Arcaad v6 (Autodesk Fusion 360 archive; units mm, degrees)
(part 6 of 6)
sketch "Sketch15" plane through (-7.6, 0, 0) normal (-1, 0, 0) x axis (0, 0, 1)
  line L1 (-31.7108, -439.5896) -> (-36.3225, -439.5896)
  line L2 (-36.3225, -423.4241) -> (-31.942, -423.4241)
  line L3 (-36.3225, -410.4241) -> (-36.3225, -423.4241)
  line L4 (-227.6775, -420.4241) -> (-46.3225, -420.4241)
  line L5 (-237.6775, -423.4241) -> (-237.6775, -410.4241)
  line L6 (-137, -423.4241) -> (-237.6775, -423.4241)
  line L7 (-137, -439.5896) -> (-137, -423.4241)
  line L8 (-237.6775, -439.5896) -> (-137, -439.5896)
  line L9 (-237.6775, -442.5896) -> (-237.6775, -439.5896)
  line L10 (-36.3225, -442.5896) -> (-237.6775, -442.5896)
  line L11 (-36.3225, -439.5896) -> (-36.3225, -442.5896)
  line L12 (-237.6775, -439.5896) -> (-237.6775, -423.4241)
  line L13 (-36.3225, -439.5896) -> (-36.3225, -423.4241)
  line L14 (-46.3225, -420.4241) -> (-227.6775, -420.4241)
  line L15
  line L16 (-227.6775, -442.5896) -> (-46.3225, -442.5896)
  line L17 (-227.6775, -420.4241) -> (-227.6775, -442.5896)
  line L18 (-242.058, -423.4241) -> (-137, -423.4241)
  line L19 (-137, -439.5896) -> (-242.2892, -439.5896)
  line L20 (-137, -423.4241) -> (-137, -439.5896)
  line L21 (-246.9266, -427.7712) -> (-237.6775, -427.7712)
  line L22 (-247.5, -435.3712) -> (-237.6775, -435.3712)
  line L23 (-42, -408.4241) -> (-38.3225, -408.4241)
  line L24 (-44, -417) -> (-44, -410.4241)
  line L25 (-230, -410.4241) -> (-230, -417)
  line L26 (-235.6775, -408.4241) -> (-232, -408.4241)
  circle C1 centre (-36.3225, -431.5712) radius 3.8
  arc A1 centre (-36.3225, -431.5712) radius 9.25 clockwise from (-31.942, -423.4241) to (-31.7108, -439.5896)
  circle C2 centre (-237.6775, -431.5712) radius 3.8
  arc A2 centre (-237.6775, -431.5712) radius 9.25 clockwise from (-242.2892, -439.5896) to (-242.058, -423.4241)
  arc A3 centre (-38.3225, -410.4241) radius 2 clockwise from (-38.3225, -408.4241) to (-36.3225, -410.4241)
  arc A4 centre (-42, -410.4241) radius 2 clockwise from (-44, -410.4241) to (-42, -408.4241)
  arc A5 centre (-47.6854, -417) radius 3.6854 clockwise from (-44, -417) to (-46.3225, -420.4241)
  arc A6 centre (-226.3146, -417) radius 3.6854 clockwise from (-227.6775, -420.4241) to (-230, -417)
  arc A7 centre (-232, -410.4241) radius 2 clockwise from (-232, -408.4241) to (-230, -410.4241)
  arc A8 centre (-235.6775, -410.4241) radius 2 clockwise from (-237.6775, -410.4241) to (-235.6775, -408.4241)
  point P9 (-237.6775, -423.4241)
  point P15 (-237.6775, -423.4241)
  point P12 (-237.6775, -439.5896)
  point P16 (-237.6775, -439.5896)
  point P6 (-36.3225, -423.4241)
  point P17 (-36.3225, -423.4241)
  point P3 (-36.3225, -439.5896)
  point P18 (-36.3225, -439.5896)
  point P28 (-237.6775, -427.7712)
  point P30 (-237.6775, -435.3712)
  coincident P9 P15
  coincident P12 P16
  coincident P6 P17
  coincident P3 P18
  coincident C2 P28
  coincident L12 P28
  tangent C2 L21
  coincident L12 P30
  coincident C2 P30
  tangent C2 L22
extrude "Extrude15" new body sketch "Sketch15" profile of C1 L1 A1 L2 L3 L4 L5 L6 L7 L8 L9 L10 L11 L12 L13 L14 L15 L16 L17 C2 L18 A2 L19 L20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 along normal blind 3
sketch "Sketch16" plane through (-11.1, 0, 0) normal (-1, 0, 0) x axis (0, 0, 1)
  circle C1 centre (-237.6775, -431.5712) radius 1.65
  circle C2 centre (-237.6775, -431.5712) radius 3.5
  circle C3 centre (-237.6775, -431.5712) radius 9.25
  circle C4 centre (-36.3225, -431.5712) radius 9.25
  circle C5 centre (-36.3225, -431.5712) radius 1.65
  circle C6 centre (-36.3225, -431.5712) radius 1.65
  circle C7 centre (-237.6775, -431.5712) radius 1.65
  circle C8 centre (-237.6775, -431.5712) radius 1.65
  point P4 (-246.111, -435.3712)
  point P5 (-36.3225, -431.5712)
  point P6 (-36.3225, -431.5712)
  concentric C1 C3
  coincident C3 P4
  coincident P5 P6
extrude "Extrude16" new body sketch "Sketch16" along normal blind 3
sketch "Sketch17" plane through (-10.6, 0, 0) normal (-1, 0, 0) x axis (0, 0, 1)
  line L1 (-246.111, -435.3712) -> (-237.6775, -435.3712)
  line L2 (-36.3225, -442.5896) -> (-237.6775, -442.5896)
  line L3 (-36.3225, -439.5896) -> (-36.3225, -442.5896)
  line L4 (-31.7108, -439.5896) -> (-36.3225, -439.5896)
  line L5 (-36.3225, -423.4241) -> (-31.942, -423.4241)
  line L6 (-36.3225, -410.4241) -> (-36.3225, -423.4241)
  line L7 (-227.6775, -420.4241) -> (-46.3225, -420.4241)
  line L8 (-237.6775, -427.7712) -> (-246.111, -427.7712)
  line L9 (-237.6775, -439.5896) -> (-242.2892, -439.5896)
  line L10 (-237.6775, -442.5896) -> (-237.6775, -439.5896)
  line L11 (-237.6775, -423.4241) -> (-237.6775, -410.4241)
  line L12 (-242.058, -423.4241) -> (-237.6775, -423.4241)
  line L13 (-42, -408.4241) -> (-38.3225, -408.4241)
  line L14 (-44, -417) -> (-44, -410.4241)
  line L15 (-230, -410.4241) -> (-230, -417)
  line L16 (-235.6775, -408.4241) -> (-232, -408.4241)
  circle C1 centre (-36.3225, -431.5712) radius 3.8
  arc A1 centre (-237.6775, -431.5712) radius 3.8 clockwise from (-237.6775, -427.7712) to (-237.6775, -435.3712)
  arc A2 centre (-237.6775, -431.5712) radius 9.25 clockwise from (-242.2892, -439.5896) to (-246.111, -435.3712)
  arc A3 centre (-36.3225, -431.5712) radius 9.25 clockwise from (-31.942, -423.4241) to (-31.7108, -439.5896)
  arc A4 centre (-237.6775, -431.5712) radius 9.25 clockwise from (-246.111, -427.7712) to (-242.058, -423.4241)
  circle C2 centre (-237.6775, -431.5712) radius 1.65
  circle C3 centre (-237.6775, -431.5712) radius 9.25
  circle C4 centre (-36.3225, -431.5712) radius 1.65
  circle C5 centre (-36.3225, -431.5712) radius 9.25
  circle C6 centre (-36.3225, -431.5712) radius 10
  circle C7 centre (-237.6775, -431.5712) radius 10
  arc A5 centre (-38.3225, -410.4241) radius 2 clockwise from (-38.3225, -408.4241) to (-36.3225, -410.4241)
  arc A6 centre (-42, -410.4241) radius 2 clockwise from (-44, -410.4241) to (-42, -408.4241)
  arc A7 centre (-47.6854, -417) radius 3.6854 clockwise from (-44, -417) to (-46.3225, -420.4241)
  arc A8 centre (-226.3146, -417) radius 3.6854 clockwise from (-227.6775, -420.4241) to (-230, -417)
  arc A9 centre (-232, -410.4241) radius 2 clockwise from (-232, -408.4241) to (-230, -410.4241)
  arc A10 centre (-235.6775, -410.4241) radius 2 clockwise from (-237.6775, -410.4241) to (-235.6775, -408.4241)
  concentric C1 C6
  concentric A1 C7
  dimension "d239" diameter C7 = 20
  dimension "d240" diameter C6 = 20
extrude "Extrude17" new body sketch "Sketch17" profile of L2 L3 L6 L7 C6 C7 along normal blind 6
sketch "Sketch18" plane through (-4.6, 0, 0) normal (-1, 0, 0) x axis (0, 0, 1)
  line L1 (-36.3225, -410.4241) -> (-36.3225, -421.5712)
  line L2 (-227.6775, -420.4241) -> (-46.3225, -420.4241)
  line L3 (-237.6775, -421.5712) -> (-237.6775, -410.4241)
  line L4 (-237.6775, -442.5896) -> (-237.6775, -441.5712)
  line L5 (-36.3225, -442.5896) -> (-237.6775, -442.5896)
  line L6 (-36.3225, -441.5712) -> (-36.3225, -442.5896)
  line L7 (-42, -408.4241) -> (-38.3225, -408.4241)
  line L8 (-44, -417) -> (-44, -410.4241)
  line L9 (-230, -410.4241) -> (-230, -417)
  line L10 (-235.6775, -408.4241) -> (-232, -408.4241)
  arc A1 centre (-237.6775, -431.5712) radius 10 clockwise from (-237.6775, -421.5712) to (-237.6775, -441.5712)
  arc A2 centre (-36.3225, -431.5712) radius 10 clockwise from (-36.3225, -441.5712) to (-36.3225, -421.5712)
  circle C1 centre (-237.6775, -431.5712) radius 1.65
  circle C2 centre (-237.6775, -431.5712) radius 9.25
  circle C3 centre (-36.3225, -431.5712) radius 1.65
  circle C4 centre (-36.3225, -431.5712) radius 9.25
  circle C5 centre (-36.3225, -431.5712) radius 10
  circle C6 centre (-237.6775, -431.5712) radius 10
  arc A3 centre (-38.3225, -410.4241) radius 2 clockwise from (-38.3225, -408.4241) to (-36.3225, -410.4241)
  arc A4 centre (-42, -410.4241) radius 2 clockwise from (-44, -410.4241) to (-42, -408.4241)
  arc A5 centre (-47.6854, -417) radius 3.6854 clockwise from (-44, -417) to (-46.3225, -420.4241)
  arc A6 centre (-226.3146, -417) radius 3.6854 clockwise from (-227.6775, -420.4241) to (-230, -417)
  arc A7 centre (-232, -410.4241) radius 2 clockwise from (-232, -408.4241) to (-230, -410.4241)
  arc A8 centre (-235.6775, -410.4241) radius 2 clockwise from (-237.6775, -410.4241) to (-235.6775, -408.4241)
  point P2 (-36.3225, -421.5712)
  point P5 (-237.6775, -421.5712)
  concentric C3 C5
  coincident P2 C5
  concentric A1 C6
  coincident P5 C6
sketch "Sketch19" plane through (-16.6, 0, 0) normal (-1, 0, 0) x axis (0, 0, 1)
  line L1 (-36.3225, -410.4241) -> (-36.3225, -421.5712)
  line L2 (-227.6775, -420.4241) -> (-46.3225, -420.4241)
  line L3 (-237.6775, -421.5712) -> (-237.6775, -410.4241)
  line L4 (-237.6775, -442.5896) -> (-237.6775, -441.5712)
  line L5 (-36.3225, -442.5896) -> (-237.6775, -442.5896)
  line L6 (-36.3225, -441.5712) -> (-36.3225, -442.5896)
  line L7 (-42, -408.4241) -> (-38.3225, -408.4241)
  line L8 (-44, -417) -> (-44, -410.4241)
  line L9 (-230, -410.4241) -> (-230, -417)
  line L10 (-235.6775, -408.4241) -> (-232, -408.4241)
  arc A1 centre (-237.6775, -431.5712) radius 10 clockwise from (-237.6775, -421.5712) to (-237.6775, -441.5712)
  arc A2 centre (-36.3225, -431.5712) radius 10 clockwise from (-36.3225, -441.5712) to (-36.3225, -421.5712)
  circle C1 centre (-237.6775, -431.5712) radius 1.65
  circle C2 centre (-237.6775, -431.5712) radius 9.25
  circle C3 centre (-36.3225, -431.5712) radius 1.65
  circle C4 centre (-36.3225, -431.5712) radius 9.25
  circle C5 centre (-36.3225, -431.5712) radius 10
  circle C6 centre (-237.6775, -431.5712) radius 10
  arc A3 centre (-38.3225, -410.4241) radius 2 clockwise from (-38.3225, -408.4241) to (-36.3225, -410.4241)
  arc A4 centre (-42, -410.4241) radius 2 clockwise from (-44, -410.4241) to (-42, -408.4241)
  arc A5 centre (-47.6854, -417) radius 3.6854 clockwise from (-44, -417) to (-46.3225, -420.4241)
  arc A6 centre (-226.3146, -417) radius 3.6854 clockwise from (-227.6775, -420.4241) to (-230, -417)
  arc A7 centre (-232, -410.4241) radius 2 clockwise from (-232, -408.4241) to (-230, -410.4241)
  arc A8 centre (-235.6775, -410.4241) radius 2 clockwise from (-237.6775, -410.4241) to (-235.6775, -408.4241)
  point P2 (-36.3225, -421.5712)
  point P5 (-237.6775, -421.5712)
  concentric A2 C5
  coincident P2 C5
  concentric A1 C6
  coincident P5 C6
extrude "Extrude18" new body sketch "Sketch19" profile of L1 L2 L3 A1 L4 L5 L6 A2 C1 C2 C3 C4 C5 C6 along normal blind 3
offset_faces "OffsetFaces1" distance 8
sketch "Sketch20" plane through (0, -420.4241, 0) normal (0, 1, 0) x axis (-1, 0, 0)
  line L1 (4.6, -34.3231) -> (0, -34.3231)
  line L2 (4.6, -24.8497) -> (4.6, -34.3231)
  line L3 (10.6, -24.8497) -> (4.6, -24.8497)
  line L4 (13, -24.8497) -> (10.6, -24.8497)
  line L5 (13, -21.8852) -> (13, -24.8497)
  line L6
  line L7 (3.6, -20.1102) -> (3.6, -21.8852)
  line L8 (13, -20.1102) -> (3.6, -20.1102)
  line L9 (13, -17.6854) -> (13, -20.1102)
  line L10 (0, -17.6854) -> (13, -17.6854)
  line L11 (0, -18.7497) -> (0, -17.6854)
  line L12 (-5.9, -18.7497) -> (0, -18.7497)
  line L13 (-5.9, -17.8497) -> (-5.9, -18.7497)
  line L14 (-7.1493, -18.2329) -> (-5.9, -17.8497)
  line L15 (-7.856, -20.4822) -> (-7.856, -19.1889)
  line L16 (0.6, -20.4822) -> (-7.856, -20.4822)
  line L17 (-5.9, -21.6169) -> (0.6, -21.601)
  line L18
  line L19 (5.2687, -23.0039) -> (-5.9, -23.0039)
  line L20 (-7.856, -24.0039) -> (5.2687, -24.0039)
  line L21 (-7.856, -24.4104) -> (-7.856, -24.0039)
  line L22 (-5.9, -25.7497) -> (-7.1493, -25.3665)
  line L23 (-5.9, -24.8497) -> (-5.9, -25.7497)
  line L24 (0, -24.8497) -> (-5.9, -24.8497)
  line L25 (0, -34.3231) -> (0, -24.8497)
  arc A1 centre (-6.856, -19.1889) radius 1 clockwise from (-7.856, -19.1889) to (-7.1493, -18.2329)
  arc A2 centre (0.6, -21.0416) radius 0.5594 clockwise from (0.6, -20.4822) to (0.6, -21.601)
  arc A3 centre (5.2687, -23.5039) radius 0.5 clockwise from (5.2687, -23.0039) to (5.2687, -24.0039)
  arc A4 centre (-6.856, -24.4104) radius 1 clockwise from (-7.1493, -25.3665) to (-7.856, -24.4104)
sketch "Sketch21" plane through (0, -442.5896, 0) normal (0, -1, 0) x axis (1, 0, 0)
  line L1 (5.9, -17.8497) -> (7.1493, -18.2329)
  line L2 (5.9, -18.7497) -> (5.9, -17.8497)
  line L3 (0, -18.7497) -> (5.9, -18.7497)
  line L4 (0, -17.6854) -> (0, -18.7497)
  line L5 (-13, -17.6854) -> (0, -17.6854)
  line L6 (-13, -20.1102) -> (-13, -17.6854)
  line L7 (-3.6, -20.1102) -> (-13, -20.1102)
  line L8 (-3.6, -21.8852) -> (-3.6, -20.1102)
  line L9
  line L10 (-13, -24.8497) -> (-13, -21.8852)
  line L11 (-10.6, -24.8497) -> (-13, -24.8497)
  line L12 (-4.6, -24.8497) -> (-10.6, -24.8497)
  line L13 (-4.6, -34.3231) -> (-4.6, -24.8497)
  line L14 (0, -34.3231) -> (-4.6, -34.3231)
  line L15 (0, -24.8497) -> (0, -34.3231)
  line L16 (5.9, -24.8497) -> (0, -24.8497)
  line L17 (5.9, -25.7497) -> (5.9, -24.8497)
  line L18 (7.1493, -25.3665) -> (5.9, -25.7497)
  line L19 (7.856, -24.0039) -> (7.856, -24.4104)
  line L20 (-5.2687, -24.0039) -> (7.856, -24.0039)
  line L21 (5.9, -23.0039) -> (-5.2687, -23.0039)
  line L22 (5.9, -21.6169) -> (5.9, -23.0039)
  line L23
  line L24 (7.856, -20.4822) -> (-0.6, -20.4822)
  line L25 (7.856, -19.1889) -> (7.856, -20.4822)
  line L26 (7.856, -20.4822) -> (7.856, -24.0039)
  arc A1 centre (6.856, -19.1889) radius 1 clockwise from (7.1493, -18.2329) to (7.856, -19.1889)
  arc A2 centre (6.856, -24.4104) radius 1 clockwise from (7.856, -24.4104) to (7.1493, -25.3665)
  arc A3 centre (-5.2687, -23.5039) radius 0.5 clockwise from (-5.2687, -24.0039) to (-5.2687, -23.0039)
  arc A4 centre (-0.6, -21.0416) radius 0.5594 clockwise from (-0.6, -21.601) to (-0.6, -20.4822)
  point P25 (7.856, -24.0039)
  point P35 (7.856, -24.0039)
  point P34 (7.856, -20.4822)
  point P36 (7.856, -20.4822)
  coincident P25 P35
  coincident P34 P36
extrude "Extrude25" add sketch "Sketch21" profile of L20 A3 L21 L22 L23 A4 L24 L26 to an object
sketch "Sketch22" plane through (7.856, 0, 0) normal (1, 0, 0) x axis (0, 0, -1)
  line L1 (24.4104, -420.4241) -> (24.4104, -442.5896)
  line L2 (19.1889, -420.4241) -> (24.4104, -420.4241)
  line L3
  line L4 (24.4104, -442.5896) -> (19.1889, -442.5896)
  line L5
  line L6 (19.1889, -442.5896) -> (24.4104, -420.4241)
  circle C1 centre (21.7997, -431.5069) radius 2.6108
  point P4 (19.1889, -420.4241)
  point P6 (19.1889, -420.4241)
  point P2 (24.4104, -442.5896)
  point P7 (24.4104, -442.5896)
  point P3 (24.4104, -420.4241)
  point P8 (24.4104, -420.4241)
  point P5 (19.1889, -442.5896)
  point P9 (19.1889, -442.5896)
  point P10 (21.7997, -431.5069)
  coincident P4 P6
  coincident P2 P7
  coincident P3 P8
  coincident P5 P9
  midpoint L5 P10
  tangent L1 C1
sketch "Sketch23" plane through (0, -420.4241, 0) normal (0, 1, 0) x axis (-1, 0, 0)
  line L1 (4.6, -34.3231) -> (0, -34.3231)
  line L2 (4.6, -24.8497) -> (4.6, -34.3231)
  line L3 (10.6, -24.8497) -> (4.6, -24.8497)
  line L4 (13, -24.8497) -> (10.6, -24.8497)
  line L5 (13, -21.8852) -> (13, -24.8497)
  line L6
  line L7 (3.6, -20.1102) -> (3.6, -21.8852)
  line L8 (13, -20.1102) -> (3.6, -20.1102)
  line L9 (13, -17.6854) -> (13, -20.1102)
  line L10 (0, -17.6854) -> (13, -17.6854)
  line L11 (0, -18.7497) -> (0, -17.6854)
  line L12 (-5.9, -18.7497) -> (0, -18.7497)
  line L13 (-5.9, -17.8497) -> (-5.9, -18.7497)
  line L14 (-7.1493, -18.2329) -> (-5.9, -17.8497)
  line L15 (-7.856, -24.4104) -> (-7.856, -19.1889)
  line L16 (-5.9, -25.7497) -> (-7.1493, -25.3665)
  line L17 (-5.9, -24.8497) -> (-5.9, -25.7497)
  line L18 (0, -24.8497) -> (-5.9, -24.8497)
  line L19 (0, -34.3231) -> (0, -24.8497)
  line L20 (0, -24.8497) -> (0, -18.7497)
  line L21 (-5.9, -25.7497) -> (-5.9, -24.8497)
  line L22 (-7.6602, -25.0049) -> (-7.3865, -25.2582)
  line L23 (-7.856, -19.1889) -> (-7.7837, -24.7838)
  line L24 (-5.9, -17.8497) -> (-7.4396, -18.3769)
  line L25 (0, -18.7497) -> (-5.9, -18.7497)
  arc A1 centre (-6.856, -19.1889) radius 1 clockwise from (-7.856, -19.1889) to (-7.1493, -18.2329)
  arc A2 centre (-6.856, -24.4104) radius 1 clockwise from (-7.1493, -25.3665) to (-7.856, -24.4104)
  point P13 (0, -18.7497)
  point P25 (0, -18.7497)
  point P24 (0, -24.8497)
  point P26 (0, -24.8497)
  point P23 (-5.9, -24.8497)
  point P27 (-5.9, -24.8497)
  point P22 (-5.9, -25.7497)
  point P28 (-5.9, -25.7497)
  point P29 (-7.3865, -25.2582)
  point P30 (-7.6602, -25.0049)
  point P31 (-7.7837, -24.7838)
  point P17 (-7.856, -19.1889)
  point P32 (-7.856, -19.1889)
  point P33 (-7.4396, -18.3769)
  point P15 (-5.9, -17.8497)
  point P34 (-5.9, -17.8497)
  point P14 (-5.9, -18.7497)
  point P35 (-5.9, -18.7497)
  point P36 (0, -18.7497)
  coincident P13 P25
  coincident P24 P26
  coincident P23 P27
  coincident P22 P28
  coincident A2 P29
  midpoint A2 P30
  coincident A2 P31
  coincident P17 P32
  coincident A1 P33
  coincident P15 P34
  coincident P14 P35
  coincident P13 P36
sketch "Sketch24" plane through (0, -420.4241, 0) normal (0, 1, 0) x axis (-1, 0, 0)
  line L1 (4.6, -34.3231) -> (0, -34.3231)
  line L2 (4.6, -24.8497) -> (4.6, -34.3231)
  line L3 (10.6, -24.8497) -> (4.6, -24.8497)
  line L4 (13, -24.8497) -> (10.6, -24.8497)
  line L5 (13, -21.8852) -> (13, -24.8497)
  line L6
  line L7 (3.6, -20.1102) -> (3.6, -21.8852)
  line L8 (13, -20.1102) -> (3.6, -20.1102)
  line L9 (13, -17.6854) -> (13, -20.1102)
  line L10 (0, -17.6854) -> (13, -17.6854)
  line L11 (0, -18.7497) -> (0, -17.6854)
  line L12 (-5.9, -18.7497) -> (0, -18.7497)
  line L13 (-5.9, -17.8497) -> (-5.9, -18.7497)
  line L14 (-7.1493, -18.2329) -> (-5.9, -17.8497)
  line L15 (-7.856, -24.4104) -> (-7.856, -19.1889)
  line L16 (-5.9, -25.7497) -> (-7.1493, -25.3665)
  line L17 (-5.9, -24.8497) -> (-5.9, -25.7497)
  line L18 (0, -24.8497) -> (-5.9, -24.8497)
  line L19 (0, -34.3231) -> (0, -24.8497)
  line L20 (-2.6535, -20.1403) -> (-7.856, -19.1889)
  line L21 (-2.6535, -20.727) -> (-2.6535, -20.1403)
  line L22 (-7.856, -20.4822) -> (-7.856, -19.1889)
  line L23 (-7.856, -19.8356) -> (-2.6535, -20.727)
  line L24
  line L25 (-2.6535, -23.459) -> (-7.856, -24.4104)
  line L26 (-7.856, -23.7638) -> (-2.6535, -22.8724)
  line L27 (-2.6535, -22.8724) -> (-2.6535, -23.459)
  arc A1 centre (-6.856, -19.1889) radius 1 clockwise from (-7.856, -19.1889) to (-7.1493, -18.2329)
  arc A2 centre (-6.856, -24.4104) radius 1 clockwise from (-7.1493, -25.3665) to (-7.856, -24.4104)
  point P17 (-7.856, -19.1889)
  point P25 (-7.856, -19.1889)
  point P30 (-7.856, -19.8356)
  point P31 (-7.856, -21.7997)
  point P33 (-7.856, -21.7997)
  coincident P17 P25
  midpoint L22 P30
  coincident P31 P33
  perpendicular L15 L24
extrude "Extrude26" cut sketch "Sketch24" profile of L15 L20 L21 L22 L23 L25 L26 L27 to an object
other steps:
derived_base_feature "Derived Base Feature"
base_feature "Base Feature1"
extrude "Extrude16" cut sketch "Sketch11" profile of L13 L17 L18 L19 L20 L21 L22 L23 L24 against normal blind 6
base_feature "Base Feature1"
create_component "CreateComponent1"
create_component "CreateComponent2"
create_component "CreateComponent4"
create_component "CreateComponent5"
create_component "CreateComponent1"
remove_body "RemoveBody1"
remove_instance "RemoveInstance1"

design "42BYGH0425"
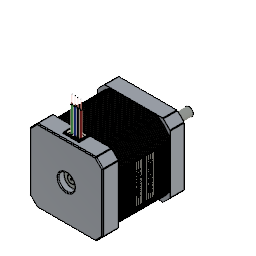
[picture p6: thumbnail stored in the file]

design "Pulley 1"
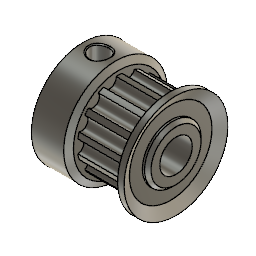
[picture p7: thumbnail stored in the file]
